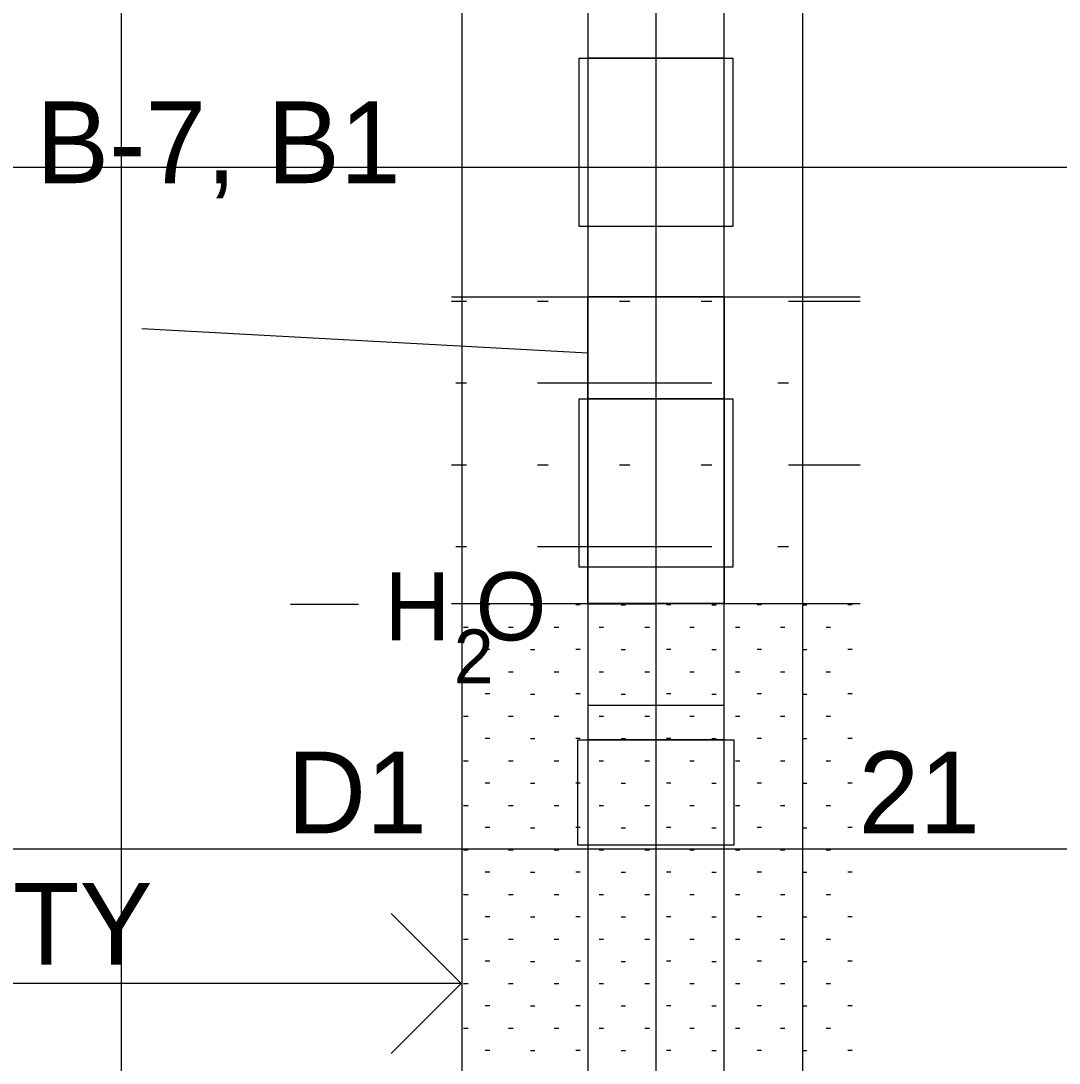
# Model space of a CAD drawing. Extents: x -290 to 297, y 616 to 861.
# Drawn here: x 137.04 to 167.52, y 703.71 to 734.3 of the extents above; entities that cross this region are included whole.
import ezdxf

# ---------------------------------------------------------------- set-up
doc = ezdxf.new("R2010")
doc.units = 0
for name, color, linetype in [('Cell', 7, 'Continuous'), ('Default', 7, 'Continuous'), ('DisROW Proposed Temp Easements', 7, 'Continuous'), ('Draft_4', 7, 'Continuous'), ('Draft_DNC', 7, 'Continuous'), ('Point', 7, 'Continuous'), ('SewerSanitary', 7, 'Continuous'), ('SewerStormIntake', 7, 'Continuous'), ('SewerStormPipe', 7, 'Continuous'), ('TextAlignment', 7, 'Continuous'), ('TextAlignmentSml', 7, 'Continuous'), ('V-SWLK-CONC', 7, 'Continuous')]:
    doc.layers.add(name, color=color, linetype=linetype)

msp = doc.modelspace()

# ---------------------------------------------------------------- linework, layer by layer
at = {"layer": 'Cell'}
msp.add_line((157.685, 714.2), (153.685, 714.2), dxfattribs=at)
at = {"layer": 'Default'}
for p, q in [((155.685, 741.2), (155.685, 680.2)), ((157.685, 726.2), (153.685, 726.2)), ((157.685, 717.2), (153.685, 717.2))]:
    msp.add_line(p, q, dxfattribs=at)
at = {"layer": 'DisROW Proposed Temp Easements'}
for p, q in [((146.954, 717.166), (144.954, 717.166)), ((153.685, 717.186), (155.685, 717.186))]:
    msp.add_line(p, q, dxfattribs=at)
for points in [[(153.43, 733.2), (157.94, 733.2), (157.94, 728.263), (153.43, 728.263)], [(153.43, 723.2), (157.94, 723.2), (157.94, 718.263), (153.43, 718.263)], [(153.397, 713.2), (157.973, 713.2), (157.973, 710.104), (153.397, 710.104)]]:
    msp.add_lwpolyline(points, close=True, dxfattribs=at)
at = {"layer": 'Draft_4'}
msp.add_lwpolyline([(157.685, 717.2), (153.685, 717.2), (153.685, 680.2), (157.685, 680.2)], close=True, dxfattribs=at)
at = {"layer": 'Draft_DNC'}
msp.add_lwpolyline([(157.685, 726.2), (153.685, 726.2), (153.685, 717.2), (157.685, 717.2)], close=True, dxfattribs=at)
at = {"layer": 'Point'}
msp.add_lwpolyline([(157.685, 740.2), (153.685, 740.2), (153.685, 726.2), (157.685, 726.2)], close=True, dxfattribs=at)
at = {"layer": 'SewerSanitary'}
for p, q in [((157.685, 733.2), (153.685, 733.2)), ((157.685, 723.2), (153.685, 723.2))]:
    msp.add_line(p, q, dxfattribs=at)
at = {"layer": 'SewerStormIntake'}
msp.add_line((157.685, 717.2), (153.685, 717.2), dxfattribs=at)
at = {"layer": 'SewerStormPipe'}
msp.add_line((157.685, 713.2), (153.685, 713.2), dxfattribs=at)
at = {"layer": 'TextAlignment'}
for p, q in [((140, 630), (140, 787.989)), ((160, 630), (160, 787.989)), ((-275.612, 730), (284.208, 730))]:
    msp.add_line(p, q, dxfattribs=at)
at = {"layer": 'TextAlignmentSml'}
for p, q in [((150, 630), (150, 787.989)), ((-275.612, 710), (284.208, 710))]:
    msp.add_line(p, q, dxfattribs=at)
at = {"layer": 'V-SWLK-CONC'}
for p, q in [((149.685, 726.2), (161.685, 726.2)), ((149.685, 726.07), (150.123, 726.07)), ((152.212, 726.07), (152.523, 726.07)), ((154.612, 726.07), (154.924, 726.07)), ((157.012, 726.07), (157.324, 726.07)), ((159.574, 726.07), (161.685, 726.07)), ((153.685, 724.547), (140.588, 725.255)), ((149.811, 723.67), (150.123, 723.67)), ((152.212, 723.67), (157.324, 723.67)), ((159.262, 723.67), (159.574, 723.67)), ((149.685, 721.27), (150.123, 721.27)), ((152.212, 721.27), (152.523, 721.27)), ((154.612, 721.27), (154.924, 721.27)), ((157.012, 721.27), (157.324, 721.27)), ((159.574, 721.27), (161.685, 721.27)), ((149.811, 718.87), (150.123, 718.87)), ((152.212, 718.87), (157.324, 718.87)), ((159.262, 718.87), (159.574, 718.87)), ((149.685, 717.2), (161.685, 717.2)), ((150.673, 717.169), (150.805, 717.169)), ((152.002, 717.155), (152.134, 717.155)), ((153.334, 717.169), (153.466, 717.169)), ((154.663, 717.155), (154.795, 717.155)), ((155.995, 717.169), (156.127, 717.169)), ((157.324, 717.155), (157.456, 717.155)), ((158.656, 717.169), (158.788, 717.169)), ((159.985, 717.155), (160.117, 717.155)), ((161.317, 717.169), (161.449, 717.169)), ((150.038, 716.502), (150.17, 716.502)), ((151.358, 716.502), (151.49, 716.502)), ((152.699, 716.502), (152.831, 716.502)), ((154.019, 716.502), (154.151, 716.502)), ((155.36, 716.502), (155.492, 716.502)), ((156.68, 716.502), (156.812, 716.502)), ((158.021, 716.502), (158.153, 716.502)), ((159.341, 716.502), (159.473, 716.502)), ((160.682, 716.502), (160.814, 716.502)), ((150.673, 715.861), (150.805, 715.861)), ((152.002, 715.848), (152.134, 715.848)), ((153.334, 715.861), (153.466, 715.861)), ((154.663, 715.848), (154.795, 715.848)), ((155.995, 715.861), (156.127, 715.861)), ((157.324, 715.848), (157.456, 715.848)), ((158.656, 715.861), (158.788, 715.861)), ((159.985, 715.848), (160.117, 715.848)), ((161.317, 715.861), (161.449, 715.861)), ((150.038, 715.194), (150.17, 715.194)), ((151.358, 715.194), (151.49, 715.194)), ((152.699, 715.194), (152.831, 715.194)), ((154.019, 715.194), (154.151, 715.194)), ((155.36, 715.194), (155.492, 715.194)), ((156.68, 715.194), (156.812, 715.194)), ((158.021, 715.194), (158.153, 715.194)), ((159.341, 715.194), (159.473, 715.194)), ((160.682, 715.194), (160.814, 715.194)), ((150.673, 714.554), (150.805, 714.554)), ((153.334, 714.554), (153.466, 714.554)), ((155.995, 714.554), (156.127, 714.554)), ((158.656, 714.554), (158.788, 714.554)), ((161.317, 714.554), (161.449, 714.554)), ((152.002, 714.54), (152.134, 714.54)), ((154.663, 714.54), (154.795, 714.54)), ((157.324, 714.54), (157.456, 714.54)), ((159.985, 714.54), (160.117, 714.54)), ((150.038, 713.887), (150.17, 713.887)), ((151.358, 713.887), (151.49, 713.887)), ((152.699, 713.887), (152.831, 713.887)), ((154.019, 713.887), (154.151, 713.887)), ((155.36, 713.887), (155.492, 713.887)), ((156.68, 713.887), (156.812, 713.887)), ((158.021, 713.887), (158.153, 713.887)), ((159.341, 713.887), (159.473, 713.887)), ((160.682, 713.887), (160.814, 713.887)), ((150.673, 713.246), (150.805, 713.246)), ((152.002, 713.233), (152.134, 713.233)), ((153.334, 713.246), (153.466, 713.246)), ((154.663, 713.233), (154.795, 713.233)), ((155.995, 713.246), (156.127, 713.246)), ((157.324, 713.233), (157.456, 713.233)), ((158.656, 713.246), (158.788, 713.246)), ((159.985, 713.233), (160.117, 713.233)), ((161.317, 713.246), (161.449, 713.246)), ((150.038, 712.579), (150.17, 712.579)), ((151.358, 712.579), (151.49, 712.579)), ((152.699, 712.579), (152.831, 712.579)), ((154.019, 712.579), (154.151, 712.579)), ((155.36, 712.579), (155.492, 712.579)), ((156.68, 712.579), (156.812, 712.579)), ((158.021, 712.579), (158.153, 712.579)), ((159.341, 712.579), (159.473, 712.579)), ((160.682, 712.579), (160.814, 712.579)), ((150.673, 711.938), (150.805, 711.938)), ((152.002, 711.925), (152.134, 711.925)), ((153.334, 711.938), (153.466, 711.938)), ((154.663, 711.925), (154.795, 711.925)), ((155.995, 711.938), (156.127, 711.938)), ((157.324, 711.925), (157.456, 711.925)), ((158.656, 711.938), (158.788, 711.938)), ((159.985, 711.925), (160.117, 711.925)), ((161.317, 711.938), (161.449, 711.938)), ((150.038, 711.272), (150.17, 711.272)), ((151.358, 711.272), (151.49, 711.272)), ((152.699, 711.272), (152.831, 711.272)), ((154.019, 711.272), (154.151, 711.272)), ((155.36, 711.272), (155.492, 711.272)), ((156.68, 711.272), (156.812, 711.272)), ((158.021, 711.272), (158.153, 711.272)), ((159.341, 711.272), (159.473, 711.272)), ((160.682, 711.272), (160.814, 711.272)), ((150.673, 710.631), (150.805, 710.631)), ((152.002, 710.618), (152.134, 710.618)), ((153.334, 710.631), (153.466, 710.631)), ((154.663, 710.618), (154.795, 710.618)), ((155.995, 710.631), (156.127, 710.631)), ((157.324, 710.618), (157.456, 710.618)), ((158.656, 710.631), (158.788, 710.631)), ((159.985, 710.618), (160.117, 710.618)), ((161.317, 710.631), (161.449, 710.631)), ((150.038, 709.964), (150.17, 709.964)), ((151.358, 709.964), (151.49, 709.964)), ((152.699, 709.964), (152.831, 709.964)), ((154.019, 709.964), (154.151, 709.964)), ((155.36, 709.964), (155.492, 709.964)), ((156.68, 709.964), (156.812, 709.964)), ((158.021, 709.964), (158.153, 709.964)), ((159.341, 709.964), (159.473, 709.964)), ((160.682, 709.964), (160.814, 709.964)), ((150.673, 709.323), (150.805, 709.323)), ((152.002, 709.31), (152.134, 709.31)), ((153.334, 709.323), (153.466, 709.323)), ((154.663, 709.31), (154.795, 709.31)), ((155.995, 709.323), (156.127, 709.323)), ((157.324, 709.31), (157.456, 709.31)), ((158.656, 709.323), (158.788, 709.323)), ((159.985, 709.31), (160.117, 709.31)), ((161.317, 709.323), (161.449, 709.323)), ((150.038, 708.656), (150.17, 708.656)), ((151.358, 708.656), (151.49, 708.656)), ((152.699, 708.656), (152.831, 708.656)), ((154.019, 708.656), (154.151, 708.656)), ((155.36, 708.656), (155.492, 708.656)), ((156.68, 708.656), (156.812, 708.656)), ((158.021, 708.656), (158.153, 708.656)), ((159.341, 708.656), (159.473, 708.656)), ((160.682, 708.656), (160.814, 708.656)), ((147.913, 708.099), (149.968, 706.044)), ((150.673, 708.016), (150.805, 708.016)), ((152.002, 708.003), (152.134, 708.003)), ((153.334, 708.016), (153.466, 708.016)), ((154.663, 708.003), (154.795, 708.003)), ((155.995, 708.016), (156.127, 708.016)), ((157.324, 708.003), (157.456, 708.003)), ((158.656, 708.016), (158.788, 708.016)), ((159.985, 708.003), (160.117, 708.003)), ((161.317, 708.016), (161.449, 708.016)), ((150.038, 707.349), (150.17, 707.349)), ((151.358, 707.349), (151.49, 707.349)), ((152.699, 707.349), (152.831, 707.349)), ((154.019, 707.349), (154.151, 707.349)), ((155.36, 707.349), (155.492, 707.349)), ((156.68, 707.349), (156.812, 707.349)), ((158.021, 707.349), (158.153, 707.349)), ((159.341, 707.349), (159.473, 707.349)), ((160.682, 707.349), (160.814, 707.349)), ((150.673, 706.708), (150.805, 706.708)), ((152.002, 706.695), (152.134, 706.695)), ((153.334, 706.708), (153.466, 706.708)), ((154.663, 706.695), (154.795, 706.695)), ((155.995, 706.708), (156.127, 706.708)), ((157.324, 706.695), (157.456, 706.695)), ((158.656, 706.708), (158.788, 706.708)), ((159.985, 706.695), (160.117, 706.695)), ((161.317, 706.708), (161.449, 706.708)), ((149.968, 706.044), (31.606, 706.044)), ((147.913, 703.989), (149.968, 706.044)), ((150.038, 706.041), (150.17, 706.041)), ((151.358, 706.041), (151.49, 706.041)), ((152.699, 706.041), (152.831, 706.041)), ((154.019, 706.041), (154.151, 706.041)), ((155.36, 706.041), (155.492, 706.041)), ((156.68, 706.041), (156.812, 706.041)), ((158.021, 706.041), (158.153, 706.041)), ((159.341, 706.041), (159.473, 706.041)), ((160.682, 706.041), (160.814, 706.041)), ((150.673, 705.401), (150.805, 705.401)), ((152.002, 705.388), (152.134, 705.388)), ((153.334, 705.401), (153.466, 705.401)), ((154.663, 705.388), (154.795, 705.388)), ((155.995, 705.401), (156.127, 705.401)), ((157.324, 705.388), (157.456, 705.388)), ((158.656, 705.401), (158.788, 705.401)), ((159.985, 705.388), (160.117, 705.388)), ((161.317, 705.401), (161.449, 705.401)), ((150.038, 704.734), (150.17, 704.734)), ((151.358, 704.734), (151.49, 704.734)), ((152.699, 704.734), (152.831, 704.734)), ((154.019, 704.734), (154.151, 704.734)), ((155.36, 704.734), (155.492, 704.734)), ((156.68, 704.734), (156.812, 704.734)), ((158.021, 704.734), (158.153, 704.734)), ((159.341, 704.734), (159.473, 704.734)), ((160.682, 704.734), (160.814, 704.734)), ((150.673, 704.093), (150.805, 704.093)), ((152.002, 704.08), (152.134, 704.08)), ((153.334, 704.093), (153.466, 704.093)), ((154.663, 704.08), (154.795, 704.08)), ((155.995, 704.093), (156.127, 704.093)), ((157.324, 704.08), (157.456, 704.08)), ((158.656, 704.093), (158.788, 704.093)), ((159.985, 704.08), (160.117, 704.08)), ((161.317, 704.093), (161.449, 704.093))]:
    msp.add_line(p, q, dxfattribs=at)
msp.add_lwpolyline([(153.685, 726.2), (157.685, 726.2), (157.685, 717.2), (153.685, 717.2)], close=True, dxfattribs=at)

# ---------------------------------------------------------------- texts
at = {"layer": 'DisROW Proposed Temp Easements'}
for s, height, p in [('H O', 2.0001, (147.717, 716.114)), ('2', 1.575, (149.751, 714.859))]:
    msp.add_text(s, height=height, dxfattribs=at).set_placement(p)
at = {"layer": 'V-SWLK-CONC'}
for s, p in [('B-7, B1', (137.49, 729.532)), ('D1', (144.859, 710.452)), ('21', (161.633, 710.452)), ('MOVED FOR CLARITY', (107.028, 706.594))]:
    msp.add_text(s, height=2.4, dxfattribs=at).set_placement(p)

doc.saveas('drawing.dxf')
